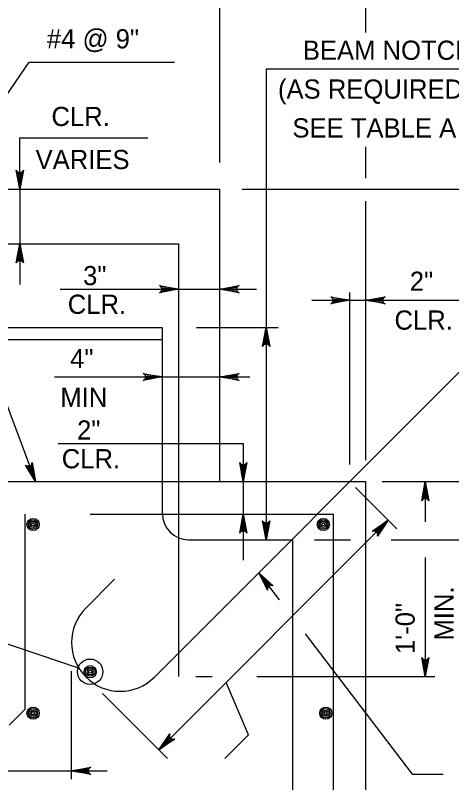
# Model space of a CAD drawing. Extents: x 640009 to 641706, y 298547 to 299735.
# Drawn here: x 641052.8 to 641121.1, y 299552.2 to 299672.2 of the extents above; entities that cross this region are included whole.
import ezdxf

# ---------------------------------------------------------------- set-up
doc = ezdxf.new("R2010")
doc.units = 0
doc.layers.add('1', color=7, linetype='Continuous')

msp = doc.modelspace()

# ---------------------------------------------------------------- linework, layer by layer
at = {"layer": '1'}
for p, q in [((641084.84, 299649.2), (641084.84, 299678.22)), ((641107.7, 299669.52), (641107.7, 299678.22)), ((641027.86, 299625.35), (641054.97, 299664.85)), ((641054.97, 299664.85), (641077.75, 299664.85)), ((641092.08, 299663.84), (641092.08, 299590.2)), ((641092.08, 299663.84), (641131.12, 299663.84)), ((641053.52, 299645), (641053.52, 299653.02)), ((641053.52, 299653.02), (641073.55, 299653.02)), ((641107.7, 299646.74), (641107.7, 299651.61)), ((640966.29, 299645), (641084.84, 299645)), ((641053.52, 299645), (641053.52, 299630.13)), ((641084.84, 299599.28), (641084.84, 299645)), ((641088.34, 299645), (641188.58, 299645)), ((641107.7, 299602.62), (641107.7, 299643.12)), ((640985.78, 299636.47), (641078.36, 299636.47)), ((641078.36, 299636.47), (641078.36, 299568.8)), ((641074.63, 299568.75), (641137.55, 299631.67)), ((641059.81, 299629.38), (641090.55, 299629.38)), ((641105.17, 299601.96), (641105.17, 299628.88)), ((641099.21, 299627.64), (641123.44, 299627.64)), ((641022.61, 299623.41), (641075.82, 299623.41)), ((641075.82, 299623.41), (641075.82, 299594.31)), ((641081.18, 299623.41), (641093.95, 299623.41)), ((641024.52, 299621.51), (641075.82, 299621.51)), ((641049.16, 299617.4), (641055.99, 299599.28)), ((641058.97, 299615.65), (641089.52, 299615.65)), ((641059.53, 299605.24), (641088.5, 299605.24)), ((641088.5, 299605.24), (641088.5, 299587.02)), ((641046.74, 299599.28), (641084.84, 299599.28)), ((641084.84, 299599.28), (641107.7, 299599.28)), ((641084.84, 299599.28), (641087.55, 299599.28)), ((641107.7, 299440.53), (641107.7, 299599.28)), ((641110.25, 299599.28), (641188.58, 299599.28)), ((641116.99, 299599.28), (641116.99, 299593)), ((641106.07, 299598.38), (641112.53, 299591.91)), ((641054.36, 299563.72), (641054.36, 299594.2)), ((641064.52, 299594.2), (641102.62, 299594.2)), ((641111.2, 299593.25), (641075.28, 299557.33)), ((641102.62, 299503.71), (641102.62, 299594.2)), ((641079.94, 299590.2), (641096.27, 299590.2)), ((641096.27, 299438.63), (641096.27, 299590.2)), ((641099.66, 299590.2), (641105.26, 299590.2)), ((641111.67, 299590.2), (641138.43, 299590.2)), ((641116.99, 299587.4), (641116.99, 299568.8)), ((641094.17, 299580.78), (641090.92, 299585.03)), ((641063.86, 299579.52), (641068.35, 299584.01)), ((641035.37, 299579.41), (641062.65, 299570.19)), ((641114.98, 299553.52), (641098.22, 299575.48)), ((641061.63, 299552.78), (641061.63, 299569.67)), ((641081.09, 299568.8), (641083.64, 299568.8)), ((641089.3, 299559.72), (641085.84, 299567.89)), ((641090.64, 299568.8), (641118.47, 299568.8)), ((641076.61, 299555.99), (641066.45, 299566.15)), ((641051.83, 299561.18), (641054.36, 299563.72)), ((641089.3, 299559.72), (641085.59, 299556.01)), ((641039.32, 299554.06), (641067.19, 299554.06)), ((641114.98, 299553.52), (641119.79, 299553.52))]:
    msp.add_line(p, q, dxfattribs=at)
for points in [[(641053.52, 299645), (641052.96, 299647.98), (641053.04, 299647.87), (641053.12, 299647.75), (641053.22, 299647.69), (641053.32, 299647.63), (641053.42, 299647.62), (641053.52, 299647.6), (641053.62, 299647.62), (641053.72, 299647.63), (641053.82, 299647.69), (641053.92, 299647.75), (641054, 299647.87), (641054.08, 299647.98), (641053.52, 299645), (641054, 299647.87), (641053.92, 299647.75), (641053.52, 299645), (641053.82, 299647.69), (641053.72, 299647.63), (641053.52, 299645), (641053.62, 299647.62), (641053.52, 299647.6), (641053.52, 299645), (641053.42, 299647.62), (641053.32, 299647.63), (641053.52, 299645), (641053.22, 299647.69), (641053.12, 299647.75), (641053.52, 299645), (641053.04, 299647.87)], [(641053.52, 299636.47), (641054.08, 299633.48), (641054, 299633.6), (641053.92, 299633.71), (641053.82, 299633.77), (641053.72, 299633.83), (641053.62, 299633.85), (641053.52, 299633.87), (641053.42, 299633.85), (641053.32, 299633.83), (641053.22, 299633.77), (641053.12, 299633.71), (641053.04, 299633.6), (641052.96, 299633.48), (641053.52, 299636.47), (641053.04, 299633.6), (641053.12, 299633.71), (641053.52, 299636.47), (641053.22, 299633.77), (641053.32, 299633.83), (641053.52, 299636.47), (641053.42, 299633.85), (641053.52, 299633.87), (641053.52, 299636.47), (641053.62, 299633.85), (641053.72, 299633.83), (641053.52, 299636.47), (641053.82, 299633.77), (641053.92, 299633.71), (641053.52, 299636.47), (641054, 299633.6)], [(641078.36, 299629.38), (641075.38, 299628.82), (641075.61, 299628.98), (641075.73, 299629.18), (641075.76, 299629.38), (641075.73, 299629.58), (641075.61, 299629.78), (641075.38, 299629.94), (641078.36, 299629.38), (641075.61, 299629.78), (641075.73, 299629.58), (641078.36, 299629.38), (641075.76, 299629.38), (641075.73, 299629.18), (641078.36, 299629.38), (641075.61, 299628.98)], [(641084.84, 299629.38), (641087.83, 299629.94), (641087.6, 299629.78), (641087.48, 299629.58), (641087.44, 299629.38), (641087.48, 299629.18), (641087.6, 299628.98), (641087.83, 299628.82), (641084.84, 299629.38), (641087.6, 299628.98), (641087.48, 299629.18), (641084.84, 299629.38), (641087.44, 299629.38), (641087.48, 299629.58), (641084.84, 299629.38), (641087.6, 299629.78)], [(641105.17, 299627.64), (641102.19, 299627.08), (641102.42, 299627.24), (641102.53, 299627.44), (641102.57, 299627.64), (641102.53, 299627.84), (641102.42, 299628.04), (641102.19, 299628.2), (641105.17, 299627.64), (641102.42, 299628.04), (641102.53, 299627.84), (641105.17, 299627.64), (641102.57, 299627.64), (641102.53, 299627.44), (641105.17, 299627.64), (641102.42, 299627.24)], [(641107.71, 299627.64), (641110.69, 299628.2), (641110.46, 299628.04), (641110.34, 299627.84), (641110.31, 299627.64), (641110.34, 299627.44), (641110.46, 299627.24), (641110.69, 299627.08), (641107.71, 299627.64), (641110.46, 299627.24), (641110.34, 299627.44), (641107.71, 299627.64), (641110.31, 299627.64), (641110.34, 299627.84), (641107.71, 299627.64), (641110.46, 299628.04)], [(641092.08, 299623.41), (641092.64, 299620.43), (641092.56, 299620.54), (641092.48, 299620.66), (641092.38, 299620.72), (641092.28, 299620.78), (641092.18, 299620.79), (641092.08, 299620.81), (641091.98, 299620.79), (641091.88, 299620.78), (641091.78, 299620.72), (641091.68, 299620.66), (641091.6, 299620.54), (641091.52, 299620.43), (641092.08, 299623.41), (641091.6, 299620.54), (641091.68, 299620.66), (641092.08, 299623.41), (641091.78, 299620.72), (641091.88, 299620.78), (641092.08, 299623.41), (641091.98, 299620.79), (641092.08, 299620.81), (641092.08, 299623.41), (641092.18, 299620.79), (641092.28, 299620.78), (641092.08, 299623.41), (641092.38, 299620.72), (641092.48, 299620.66), (641092.08, 299623.41), (641092.56, 299620.54)], [(641075.82, 299615.65), (641072.84, 299615.09), (641073.07, 299615.25), (641073.19, 299615.45), (641073.22, 299615.65), (641073.19, 299615.85), (641073.07, 299616.05), (641072.84, 299616.21), (641075.82, 299615.65), (641073.07, 299616.05), (641073.19, 299615.85), (641075.82, 299615.65), (641073.22, 299615.65), (641073.19, 299615.45), (641075.82, 299615.65), (641073.07, 299615.25)], [(641084.84, 299615.65), (641087.83, 299616.21), (641087.6, 299616.05), (641087.48, 299615.85), (641087.44, 299615.65), (641087.48, 299615.45), (641087.6, 299615.25), (641087.83, 299615.09), (641084.84, 299615.65), (641087.6, 299615.25), (641087.48, 299615.45), (641084.84, 299615.65), (641087.44, 299615.65), (641087.48, 299615.85), (641084.84, 299615.65), (641087.6, 299616.05)], [(641055.99, 299599.28), (641054.41, 299601.87), (641054.53, 299601.8), (641054.64, 299601.72), (641054.76, 299601.7), (641054.87, 299601.68), (641054.97, 299601.69), (641055.07, 299601.71), (641055.16, 299601.76), (641055.24, 299601.82), (641055.32, 299601.91), (641055.39, 299602), (641055.42, 299602.13), (641055.46, 299602.27), (641055.99, 299599.28), (641055.42, 299602.13), (641055.39, 299602), (641055.99, 299599.28), (641055.32, 299601.91), (641055.24, 299601.82), (641055.99, 299599.28), (641055.16, 299601.76), (641055.07, 299601.71), (641055.99, 299599.28), (641054.97, 299601.69), (641054.87, 299601.68), (641055.99, 299599.28), (641054.76, 299601.7), (641054.64, 299601.72), (641055.99, 299599.28), (641054.53, 299601.8)], [(641088.5, 299599.28), (641087.94, 299602.26), (641088.02, 299602.15), (641088.1, 299602.03), (641088.2, 299601.97), (641088.3, 299601.91), (641088.4, 299601.9), (641088.5, 299601.88), (641088.6, 299601.9), (641088.7, 299601.91), (641088.8, 299601.97), (641088.9, 299602.03), (641088.98, 299602.15), (641089.06, 299602.26), (641088.5, 299599.28), (641088.98, 299602.15), (641088.9, 299602.03), (641088.5, 299599.28), (641088.8, 299601.97), (641088.7, 299601.91), (641088.5, 299599.28), (641088.6, 299601.9), (641088.5, 299601.88), (641088.5, 299599.28), (641088.4, 299601.9), (641088.3, 299601.91), (641088.5, 299599.28), (641088.2, 299601.97), (641088.1, 299602.03), (641088.5, 299599.28), (641088.02, 299602.15)], [(641116.99, 299599.28), (641117.55, 299596.3), (641117.47, 299596.41), (641117.39, 299596.53), (641117.29, 299596.59), (641117.19, 299596.65), (641117.09, 299596.66), (641116.99, 299596.68), (641116.89, 299596.66), (641116.79, 299596.65), (641116.69, 299596.59), (641116.59, 299596.53), (641116.51, 299596.41), (641116.43, 299596.3), (641116.99, 299599.28), (641116.51, 299596.41), (641116.59, 299596.53), (641116.99, 299599.28), (641116.69, 299596.59), (641116.79, 299596.65), (641116.99, 299599.28), (641116.89, 299596.66), (641116.99, 299596.68), (641116.99, 299599.28), (641117.09, 299596.66), (641117.19, 299596.65), (641116.99, 299599.28), (641117.29, 299596.59), (641117.39, 299596.53), (641116.99, 299599.28), (641117.47, 299596.41)], [(641088.5, 299594.2), (641089.06, 299591.22), (641088.98, 299591.33), (641088.9, 299591.45), (641088.8, 299591.51), (641088.7, 299591.57), (641088.6, 299591.58), (641088.5, 299591.6), (641088.4, 299591.58), (641088.3, 299591.57), (641088.2, 299591.51), (641088.1, 299591.45), (641088.02, 299591.33), (641087.94, 299591.22), (641088.5, 299594.2), (641088.02, 299591.33), (641088.1, 299591.45), (641088.5, 299594.2), (641088.2, 299591.51), (641088.3, 299591.57), (641088.5, 299594.2), (641088.4, 299591.58), (641088.5, 299591.6), (641088.5, 299594.2), (641088.6, 299591.58), (641088.7, 299591.57), (641088.5, 299594.2), (641088.8, 299591.51), (641088.9, 299591.45), (641088.5, 299594.2), (641088.98, 299591.33)], [(641092.08, 299590.2), (641091.52, 299593.18), (641091.6, 299593.07), (641091.68, 299592.95), (641091.78, 299592.89), (641091.88, 299592.83), (641091.98, 299592.82), (641092.08, 299592.8), (641092.18, 299592.82), (641092.28, 299592.83), (641092.38, 299592.89), (641092.48, 299592.95), (641092.56, 299593.07), (641092.64, 299593.18), (641092.08, 299590.2), (641092.56, 299593.07), (641092.48, 299592.95), (641092.08, 299590.2), (641092.38, 299592.89), (641092.28, 299592.83), (641092.08, 299590.2), (641092.18, 299592.82), (641092.08, 299592.8), (641092.08, 299590.2), (641091.98, 299592.82), (641091.88, 299592.83), (641092.08, 299590.2), (641091.78, 299592.89), (641091.68, 299592.95), (641092.08, 299590.2), (641091.6, 299593.07)], [(641111.2, 299593.25), (641109.49, 299590.74), (641109.51, 299590.88), (641109.54, 299591.02), (641109.51, 299591.13), (641109.48, 299591.24), (641109.42, 299591.33), (641109.36, 299591.41), (641109.28, 299591.47), (641109.2, 299591.53), (641109.08, 299591.55), (641108.97, 299591.58), (641108.83, 299591.56), (641108.69, 299591.53), (641111.2, 299593.25), (641108.83, 299591.56), (641108.97, 299591.58), (641111.2, 299593.25), (641109.08, 299591.55), (641109.2, 299591.53), (641111.2, 299593.25), (641109.28, 299591.47), (641109.36, 299591.41), (641111.2, 299593.25), (641109.42, 299591.33), (641109.48, 299591.24), (641111.2, 299593.25), (641109.51, 299591.13), (641109.54, 299591.02), (641111.2, 299593.25), (641109.51, 299590.88)], [(641090.92, 299585.03), (641093.17, 299583), (641093.04, 299583.05), (641092.91, 299583.09), (641092.79, 299583.07), (641092.68, 299583.06), (641092.59, 299583.01), (641092.5, 299582.97), (641092.43, 299582.89), (641092.36, 299582.82), (641092.32, 299582.71), (641092.27, 299582.6), (641092.28, 299582.46), (641092.28, 299582.32), (641090.92, 299585.03), (641092.28, 299582.46), (641092.27, 299582.6), (641090.92, 299585.03), (641092.32, 299582.71), (641092.36, 299582.82), (641090.92, 299585.03), (641092.43, 299582.89), (641092.5, 299582.97), (641090.92, 299585.03), (641092.59, 299583.01), (641092.68, 299583.06), (641090.92, 299585.03), (641092.79, 299583.07), (641092.91, 299583.09), (641090.92, 299585.03), (641093.04, 299583.05)], [(641090.92, 299585.03), (641093.17, 299583), (641093.04, 299583.05), (641092.91, 299583.09), (641092.79, 299583.07), (641092.68, 299583.06), (641092.59, 299583.01), (641092.5, 299582.97), (641092.43, 299582.89), (641092.36, 299582.82), (641092.32, 299582.71), (641092.27, 299582.6), (641092.28, 299582.46), (641092.28, 299582.32), (641090.92, 299585.03), (641092.28, 299582.46), (641092.27, 299582.6), (641090.92, 299585.03), (641092.32, 299582.71), (641092.36, 299582.82), (641090.92, 299585.03), (641092.43, 299582.89), (641092.5, 299582.97), (641090.92, 299585.03), (641092.59, 299583.01), (641092.68, 299583.06), (641090.92, 299585.03), (641092.79, 299583.07), (641092.91, 299583.09), (641090.92, 299585.03), (641093.04, 299583.05)], [(641116.99, 299568.8), (641116.43, 299571.78), (641116.51, 299571.67), (641116.59, 299571.55), (641116.69, 299571.49), (641116.79, 299571.43), (641116.89, 299571.42), (641116.99, 299571.4), (641117.09, 299571.42), (641117.19, 299571.43), (641117.29, 299571.49), (641117.39, 299571.55), (641117.47, 299571.67), (641117.55, 299571.78), (641116.99, 299568.8), (641117.47, 299571.67), (641117.39, 299571.55), (641116.99, 299568.8), (641117.29, 299571.49), (641117.19, 299571.43), (641116.99, 299568.8), (641117.09, 299571.42), (641116.99, 299571.4), (641116.99, 299568.8), (641116.89, 299571.42), (641116.79, 299571.43), (641116.99, 299568.8), (641116.69, 299571.49), (641116.59, 299571.55), (641116.99, 299568.8), (641116.51, 299571.67)], [(641075.28, 299557.33), (641076.99, 299559.83), (641076.97, 299559.69), (641076.94, 299559.55), (641076.97, 299559.44), (641077, 299559.33), (641077.06, 299559.25), (641077.12, 299559.16), (641077.2, 299559.11), (641077.28, 299559.05), (641077.39, 299559.02), (641077.51, 299558.99), (641077.64, 299559.01), (641077.78, 299559.04), (641075.28, 299557.33), (641077.64, 299559.01), (641077.51, 299558.99), (641075.28, 299557.33), (641077.39, 299559.02), (641077.28, 299559.05), (641075.28, 299557.33), (641077.2, 299559.11), (641077.12, 299559.16), (641075.28, 299557.33), (641077.06, 299559.25), (641077, 299559.33), (641075.28, 299557.33), (641076.97, 299559.44), (641076.94, 299559.55), (641075.28, 299557.33), (641076.97, 299559.69)], [(641061.63, 299554.06), (641064.61, 299554.62), (641064.49, 299554.54), (641064.38, 299554.46), (641064.32, 299554.36), (641064.26, 299554.26), (641064.24, 299554.16), (641064.23, 299554.06), (641064.24, 299553.96), (641064.26, 299553.86), (641064.32, 299553.76), (641064.38, 299553.66), (641064.49, 299553.58), (641064.61, 299553.5), (641061.63, 299554.06), (641064.49, 299553.58), (641064.38, 299553.66), (641061.63, 299554.06), (641064.32, 299553.76), (641064.26, 299553.86), (641061.63, 299554.06), (641064.24, 299553.96), (641064.23, 299554.06), (641061.63, 299554.06), (641064.24, 299554.16), (641064.26, 299554.26), (641061.63, 299554.06), (641064.32, 299554.36), (641064.38, 299554.46), (641061.63, 299554.06), (641064.49, 299554.54)]]:
    msp.add_lwpolyline(points, dxfattribs=at)
for centre, radius in [((641055.59, 299592.59), 0.952), ((641055.59, 299592.59), 0.714), ((641055.59, 299592.59), 0.476), ((641101.03, 299592.59), 0.952), ((641101.03, 299592.59), 0.714), ((641101.03, 299592.59), 0.476), ((641055.59, 299592.59), 0.238), ((641101.03, 299592.59), 0.238), ((641064.53, 299569.56), 1.99), ((641064.53, 299569.56), 0.952), ((641064.53, 299569.56), 0.714), ((641064.53, 299569.56), 0.476), ((641064.53, 299569.56), 0.238), ((641055.59, 299563.08), 0.952), ((641055.59, 299563.08), 0.714), ((641055.59, 299563.08), 0.476), ((641055.59, 299563.08), 0.238), ((641101.41, 299563.08), 0.952), ((641101.41, 299563.08), 0.714), ((641101.41, 299563.08), 0.476), ((641101.41, 299563.08), 0.238)]:
    msp.add_circle(centre, radius, dxfattribs=at)
for centre, radius, start, end in [((641079.94, 299594.31), 4.11, 180, 270), ((641069.24, 299574.13), 7.62, 135, 315)]:
    msp.add_arc(centre, radius, start, end, dxfattribs=at)

# ---------------------------------------------------------------- texts
for s, p in [('#4 @ 9"', (641057.76, 299667.03)), ('BEAM NOTCH', (641097.82, 299665.24)), ('(AS REQUIRED)', (641093.93, 299659.17)), ('CLR.', (641058.47, 299654.88)), ('SEE TABLE A', (641096.19, 299653.09)), ('VARIES', (641055.98, 299648.15)), ('3"', (641063.42, 299630)), ('2"', (641114.57, 299629.12)), ('CLR.', (641061.02, 299625.52)), ('CLR.', (641112.17, 299623.05)), ('4"', (641061.39, 299617.03)), ('MIN', (641059.86, 299610.96)), ('2"', (641062.48, 299605.86)), ('CLR.', (641060.08, 299601.37))]:
    msp.add_text(s, height=3, dxfattribs=at).set_placement(p)
for s, p in [('MIN.', (641121.41, 299574.43)), ('1\'-0"', (641115.33, 299572.33))]:
    msp.add_text(s, height=3, rotation=90, dxfattribs=at).set_placement(p)

doc.saveas('drawing.dxf')
